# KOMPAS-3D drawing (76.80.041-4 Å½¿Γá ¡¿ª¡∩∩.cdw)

Views: Вид 1
Referenced files in C:\Users\ptitsin\Desktop\Базовая грузовые\: ПТФ 436200.20.041 Плита нижняя.cdw
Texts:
  Острые кромки притупить R0,5мм.
  H14, h14,  IT 14/2.
  Ra 6,3
  Ra 6,3 ( )
  невидимая2_RGB_0_0_0_SC_1_THICK_-0.03
  невидимая_RGB_0_0_0_SC_1_THICK_-0.03
  невидимая2_RGB_0_0_0_SC_1_THICK_0.18
  GOST2.303 5_RGB_255_0_0_SC_1_THICK_0.18
  невидимая_RGB_0_0_0_SC_1_THICK_0.18
  GOST2.303 5_RGB_255_0_0_SC_1_THICK_0.25
  Плита нижняя
  Т. директор
  Ст3 ГОСТ 380-94
  ООО "ЗАВОД МАРКОН"
Dimensions and other numbers on the sheet: 410; 45; 28; 4 паза; 1х45; 50; 4 отв.; 12; 95; 370; 470; 0,8; 62; 200; 2; 14; 0,02; 3,2; 4; 1:1; 1; 76.80.041-4; 76.80.041-4-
